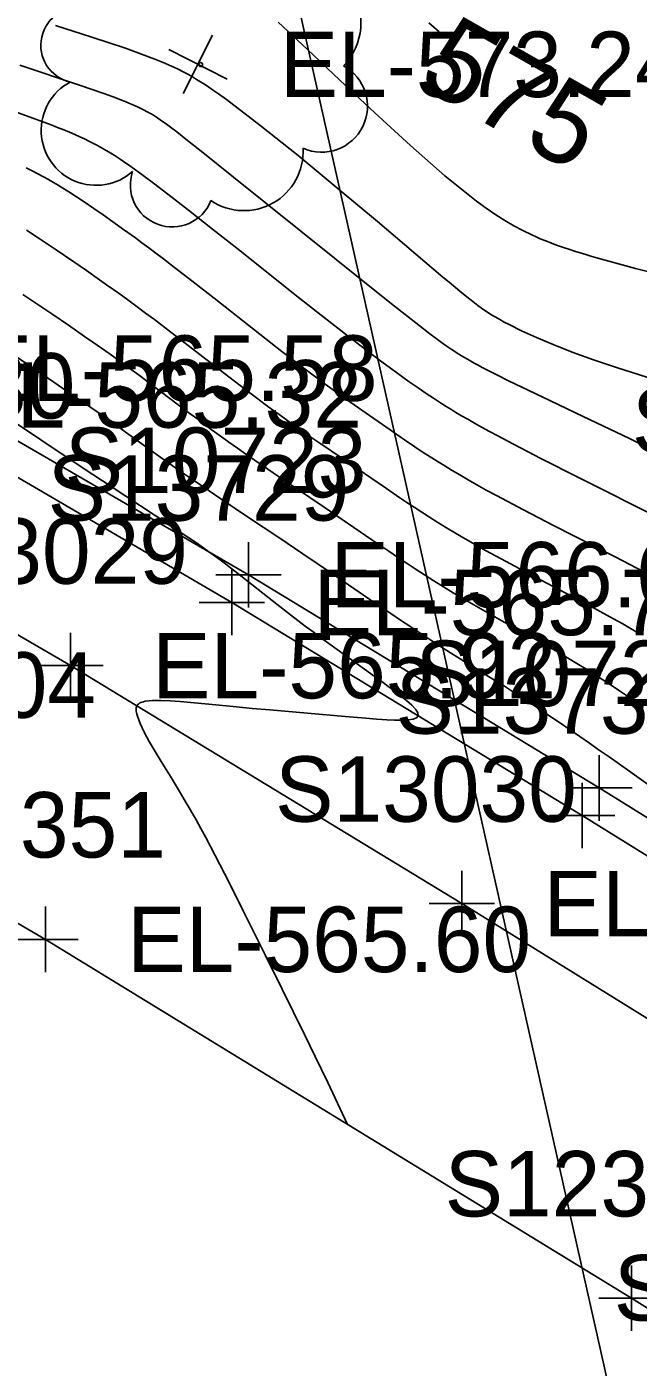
# Model space of a CAD drawing. Extents: x 1729869 to 1735532, y 648588 to 653771.
# Drawn here: x 1730731.9 to 1730769.3, y 652374.7 to 652456.6 of the extents above; entities that cross this region are included whole.
import ezdxf

# ---------------------------------------------------------------- set-up
doc = ezdxf.new("R2010")
doc.units = 0
for name, color, linetype in [('SURVEY - CONTOURS - Index with Text', 7, 'Continuous'), ('SURVEY - CONTOURS - Intermediate with optional Text', 7, 'Continuous'), ('SURVEY - DRAINAGE - Storm Sewer Text', 7, 'Continuous'), ('SURVEY - DTM - Breaklines', 7, 'Continuous'), ('SURVEY - DTM - Breaklines - Points - Elevations', 7, 'Continuous'), ('SURVEY - DTM - Breaklines - Points - Locators', 7, 'Continuous'), ('SURVEY - DTM - Breaklines - Points - Numbers', 7, 'Continuous'), ('SURVEY - TRANSPORTATION - Features', 7, 'Continuous'), ('SURVEY - TRANSPORTATION - Features - Points - Elevations', 7, 'Continuous'), ('SURVEY - TRANSPORTATION - Features - Points - Locators', 7, 'Continuous'), ('SURVEY - TRANSPORTATION - Features - Points - Numbers', 7, 'Continuous'), ('SURVEY - TRANSPORTATION - Roads', 7, 'Continuous'), ('SURVEY - TRANSPORTATION - Roads - Points - Elevations', 7, 'Continuous'), ('SURVEY - TRANSPORTATION - Roads - Points - Locators', 7, 'Continuous'), ('SURVEY - TRANSPORTATION - Roads - Points - Numbers', 7, 'Continuous'), ('SURVEY - UTILITIES - Poles and Miscellaneous - Points - Numbers', 7, 'Continuous'), ('SURVEY - VEGETATION - Features - Points - Elevations', 7, 'Continuous'), ('SURVEY - VEGETATION - Features - Points - Locators', 7, 'Continuous'), ('SURVEY - VEGETATION - Features with Text', 7, 'Continuous')]:
    doc.layers.add(name, color=color, linetype=linetype)

msp = doc.modelspace()

# ---------------------------------------------------------------- linework, layer by layer
at = {"layer": 'SURVEY - CONTOURS - Index with Text'}
for points in [[(1730757.118, 652456.338), (1730756.499, 652456.887)], [(1730769.662, 652423.314), (1730767.88, 652424.234), (1730764.101, 652426.166), (1730762.28, 652427.108), (1730760.621, 652427.988), (1730760.003, 652428.325), (1730759.425, 652428.647), (1730758.884, 652428.954), (1730758.379, 652429.247), (1730757.906, 652429.527), (1730757.463, 652429.795), (1730757.053, 652430.048), (1730756.667, 652430.291), (1730756.302, 652430.525), (1730755.956, 652430.752), (1730755.625, 652430.971), (1730755.002, 652431.391), (1730754.121, 652431.996), (1730752.387, 652433.198), (1730751.714, 652433.671), (1730751.353, 652433.928), (1730750.977, 652434.198), (1730750.581, 652434.486), (1730750.163, 652434.793), (1730749.723, 652435.12), (1730749.257, 652435.469), (1730748.766, 652435.841), (1730747.515, 652436.802), (1730746.164, 652437.855), (1730743.362, 652440.052), (1730742.01, 652441.108), (1730740.757, 652442.076), (1730740.269, 652442.45), (1730739.805, 652442.8), (1730739.366, 652443.13), (1730738.95, 652443.439), (1730738.555, 652443.73), (1730737.83, 652444.257), (1730737.177, 652444.723), (1730736.577, 652445.144), (1730736.018, 652445.53), (1730735.487, 652445.891), (1730734.965, 652446.239), (1730734.493, 652446.545), (1730734.118, 652446.783), (1730733.84, 652446.953), (1730733.552, 652447.126), (1730733.251, 652447.3), (1730732.934, 652447.477), (1730732.599, 652447.657), (1730732.248, 652447.838), (1730731.877, 652448.022)]]:
    msp.add_lwpolyline(points, dxfattribs=at)
at = {"layer": 'SURVEY - CONTOURS - Intermediate with optional Text'}
for points in [[(1730770.268, 652435.091), (1730767.969, 652435.806), (1730766.551, 652436.288), (1730765.259, 652436.761), (1730764.094, 652437.218), (1730763.06, 652437.655), (1730762.159, 652438.064), (1730761.392, 652438.439), (1730761.1, 652438.592), (1730760.83, 652438.739), (1730760.58, 652438.881), (1730760.349, 652439.019), (1730760.129, 652439.158), (1730759.916, 652439.3), (1730759.705, 652439.447), (1730759.491, 652439.604), (1730759.174, 652439.846), (1730758.802, 652440.142), (1730758.38, 652440.486), (1730757.726, 652441.029), (1730757.354, 652441.342), (1730753.346, 652444.73), (1730750.944, 652446.744), (1730748.495, 652448.764), (1730746.164, 652450.633), (1730744.114, 652452.195), (1730743.638, 652452.538), (1730743.336, 652452.75), (1730743.047, 652452.947), (1730742.77, 652453.13), (1730742.5, 652453.302), (1730742.236, 652453.464), (1730741.978, 652453.615), (1730741.719, 652453.76), (1730741.434, 652453.911), (1730741.172, 652454.043), (1730740.904, 652454.171), (1730740.628, 652454.298), (1730740.345, 652454.421), (1730740.052, 652454.544), (1730739.747, 652454.668), (1730737.948, 652455.329), (1730735.891, 652456.009), (1730733.671, 652456.707)], [(1730772.169, 652441.094), (1730769.12, 652441.872), (1730766.46, 652442.604), (1730766.087, 652442.715), (1730765.729, 652442.824), (1730765.384, 652442.932), (1730765.051, 652443.039), (1730764.73, 652443.147), (1730764.419, 652443.255), (1730764.129, 652443.359), (1730763.848, 652443.466), (1730763.573, 652443.574), (1730763.304, 652443.684), (1730763.04, 652443.798), (1730762.779, 652443.916), (1730762.231, 652444.181), (1730761.686, 652444.472), (1730761.137, 652444.792), (1730760.578, 652445.148), (1730760, 652445.543), (1730759.397, 652445.984), (1730757.471, 652447.533), (1730755.37, 652449.375), (1730753.198, 652451.37), (1730751.058, 652453.384), (1730749.052, 652455.278), (1730747.285, 652456.915)], [(1730771.773, 652429.989), (1730768.748, 652431.466), (1730765.919, 652432.824), (1730763.415, 652434.019), (1730761.368, 652435.008), (1730760.647, 652435.365), (1730760.027, 652435.681), (1730759.751, 652435.824), (1730759.497, 652435.959), (1730759.265, 652436.085), (1730759.05, 652436.203), (1730758.85, 652436.316), (1730758.663, 652436.425), (1730758.488, 652436.53), (1730758.321, 652436.632), (1730758.163, 652436.732), (1730758.01, 652436.832), (1730757.859, 652436.932), (1730757.556, 652437.141), (1730757.272, 652437.344), (1730756.933, 652437.593), (1730756.551, 652437.88), (1730755.873, 652438.401), (1730755.041, 652439.05), (1730754.388, 652439.565), (1730752.688, 652440.918), (1730750.717, 652442.499), (1730744.555, 652447.457), (1730742.57, 652449.046), (1730741.749, 652449.697), (1730741.079, 652450.219), (1730740.706, 652450.504), (1730740.374, 652450.749), (1730740.219, 652450.859), (1730740.073, 652450.96), (1730739.931, 652451.056), (1730739.791, 652451.147), (1730739.652, 652451.234), (1730739.513, 652451.317), (1730739.284, 652451.446), (1730739.045, 652451.572), (1730738.886, 652451.651), (1730738.719, 652451.73), (1730738.541, 652451.811), (1730738.352, 652451.894), (1730738.15, 652451.979), (1730737.936, 652452.066), (1730737.707, 652452.157), (1730737.463, 652452.25), (1730737.202, 652452.348), (1730736.629, 652452.556), (1730735.146, 652453.068), (1730731.485, 652454.291)], [(1730770.62, 652426.587), (1730765.684, 652429.068), (1730763.333, 652430.263), (1730761.268, 652431.335), (1730760.712, 652431.632), (1730760.195, 652431.91), (1730759.717, 652432.173), (1730759.275, 652432.419), (1730758.867, 652432.65), (1730758.491, 652432.867), (1730758.149, 652433.069), (1730757.833, 652433.259), (1730757.54, 652433.439), (1730757.267, 652433.61), (1730757.011, 652433.774), (1730756.77, 652433.931), (1730756.322, 652434.23), (1730755.896, 652434.522), (1730755.297, 652434.942), (1730754.6, 652435.44), (1730754.069, 652435.826), (1730753.468, 652436.271), (1730752.785, 652436.785), (1730752.006, 652437.38), (1730751.577, 652437.711), (1730750.092, 652438.871), (1730748.43, 652440.182), (1730744.933, 652442.956), (1730743.275, 652444.27), (1730741.795, 652445.433), (1730740.987, 652446.062), (1730740.276, 652446.608), (1730739.654, 652447.08), (1730739.116, 652447.482), (1730738.641, 652447.83), (1730738.212, 652448.137), (1730737.819, 652448.409), (1730737.63, 652448.537), (1730737.441, 652448.661), (1730737.253, 652448.783), (1730736.946, 652448.973), (1730736.627, 652449.162), (1730736.416, 652449.281), (1730736.195, 652449.402), (1730735.96, 652449.526), (1730735.709, 652449.652), (1730735.441, 652449.782), (1730735.157, 652449.914), (1730734.852, 652450.051), (1730734.526, 652450.192), (1730734.177, 652450.338), (1730733.803, 652450.489), (1730733.405, 652450.645), (1730732.069, 652451.142), (1730730.557, 652451.68)], [(1730769.366, 652419.546), (1730768.865, 652419.841), (1730768.338, 652420.144), (1730767.782, 652420.457), (1730766.563, 652421.123), (1730765.258, 652421.817), (1730762.545, 652423.244), (1730761.217, 652423.95), (1730759.962, 652424.635), (1730759.318, 652424.996), (1730758.706, 652425.348), (1730758.124, 652425.691), (1730757.569, 652426.024), (1730757.039, 652426.349), (1730756.533, 652426.666), (1730756.054, 652426.972), (1730755.594, 652427.271), (1730755.15, 652427.564), (1730754.72, 652427.851), (1730753.894, 652428.41), (1730751.275, 652430.205), (1730749.703, 652431.277), (1730749.286, 652431.564), (1730748.856, 652431.863), (1730748.416, 652432.171), (1730747.961, 652432.494), (1730747.49, 652432.832), (1730747, 652433.187), (1730746.492, 652433.561), (1730745.964, 652433.954), (1730744.962, 652434.711), (1730743.914, 652435.514), (1730741.77, 652437.169), (1730740.719, 652437.977), (1730739.713, 652438.741), (1730739.18, 652439.14), (1730738.667, 652439.52), (1730738.173, 652439.883), (1730737.696, 652440.228), (1730737.236, 652440.558), (1730736.792, 652440.874), (1730736.367, 652441.173), (1730735.557, 652441.736), (1730734.789, 652442.263), (1730733.705, 652442.999), (1730732.664, 652443.698), (1730731.907, 652444.198)], [(1730769.615, 652415.045), (1730769.13, 652415.383), (1730768.639, 652415.72), (1730768.141, 652416.057), (1730767.635, 652416.394), (1730767.127, 652416.727), (1730766.608, 652417.061), (1730766.076, 652417.395), (1730765.531, 652417.731), (1730764.97, 652418.069), (1730764.393, 652418.409), (1730763.56, 652418.886), (1730762.702, 652419.367), (1730760.956, 652420.335), (1730760.087, 652420.821), (1730759.236, 652421.307), (1730758.603, 652421.677), (1730757.985, 652422.047), (1730757.382, 652422.416), (1730756.792, 652422.783), (1730756.215, 652423.149), (1730755.651, 652423.513), (1730755.105, 652423.871), (1730754.568, 652424.227), (1730754.041, 652424.58), (1730753.012, 652425.278), (1730750.084, 652427.279), (1730749.226, 652427.861), (1730747.311, 652429.151), (1730746.321, 652429.824), (1730745.822, 652430.167), (1730745.314, 652430.52), (1730744.798, 652430.882), (1730744.272, 652431.255), (1730743.738, 652431.639), (1730743.194, 652432.035), (1730742.446, 652432.587), (1730741.686, 652433.155), (1730740.152, 652434.31), (1730739.389, 652434.881), (1730738.637, 652435.44), (1730738.083, 652435.845), (1730737.539, 652436.239), (1730737.003, 652436.623), (1730736.475, 652436.997), (1730735.956, 652437.361), (1730735.445, 652437.717), (1730734.458, 652438.396), (1730733.5, 652439.047), (1730731.671, 652440.28)], [(1730751.522, 652389.556), (1730750.307, 652392.108), (1730749.544, 652393.699), (1730748.89, 652395.044), (1730747.532, 652397.812), (1730746.487, 652399.929), (1730745.149, 652402.617), (1730744.469, 652403.974), (1730744.008, 652404.883), (1730743.724, 652405.435), (1730743.438, 652405.987), (1730743.148, 652406.538), (1730742.855, 652407.087), (1730742.559, 652407.631), (1730742.26, 652408.17), (1730741.906, 652408.796), (1730741.543, 652409.42), (1730741.168, 652410.049), (1730740.744, 652410.747), (1730740.139, 652411.73), (1730739.76, 652412.355), (1730739.406, 652412.962), (1730739.095, 652413.533), (1730738.845, 652414.051), (1730738.674, 652414.5), (1730738.64, 652414.624), (1730738.616, 652414.738), (1730738.605, 652414.815), (1730738.6, 652414.887), (1730738.601, 652414.954), (1730738.608, 652415.017), (1730738.622, 652415.074), (1730738.643, 652415.127), (1730738.668, 652415.171), (1730738.7, 652415.211), (1730738.737, 652415.248), (1730738.781, 652415.281), (1730738.83, 652415.31), (1730738.885, 652415.337), (1730738.96, 652415.365), (1730739.042, 652415.389), (1730739.152, 652415.414), (1730739.194, 652415.421), (1730739.606, 652415.464), (1730740.104, 652415.471), (1730740.671, 652415.449), (1730741.289, 652415.406), (1730741.942, 652415.348), (1730743.039, 652415.239), (1730744.74, 652415.068), (1730745.697, 652414.978), (1730746.762, 652414.883), (1730751.385, 652414.488), (1730752.647, 652414.379), (1730753.296, 652414.328), (1730753.61, 652414.305), (1730753.916, 652414.286), (1730754.4, 652414.264), (1730754.842, 652414.258), (1730755.224, 652414.275), (1730755.53, 652414.32), (1730755.744, 652414.401), (1730755.847, 652414.524), (1730755.826, 652414.7), (1730755.686, 652414.921), (1730755.446, 652415.179), (1730755.124, 652415.467), (1730754.74, 652415.778), (1730754.311, 652416.106), (1730754.012, 652416.327), (1730753.704, 652416.553), (1730753.066, 652417.011), (1730751.901, 652417.843), (1730750.886, 652418.576), (1730750.386, 652418.94), (1730749.895, 652419.301), (1730749.415, 652419.657), (1730748.94, 652420.012), (1730748.481, 652420.36), (1730748.036, 652420.7), (1730747.196, 652421.35), (1730746.344, 652422.017), (1730744.997, 652423.08), (1730744.375, 652423.563), (1730744.056, 652423.808), (1730743.729, 652424.054), (1730743.395, 652424.301), (1730743.051, 652424.55), (1730742.741, 652424.77), (1730742.424, 652424.991), (1730742.098, 652425.215), (1730741.422, 652425.67), (1730740.532, 652426.261), (1730737.129, 652428.494), (1730735.361, 652429.666), (1730732.77, 652431.392), (1730725.722, 652436.103)], [(1730770.622, 652409.793), (1730768.775, 652411.115), (1730767.505, 652412.015), (1730766.907, 652412.437), (1730766.31, 652412.855), (1730765.715, 652413.268), (1730765.123, 652413.677), (1730764.534, 652414.08), (1730763.956, 652414.471), (1730763.381, 652414.856), (1730762.808, 652415.236), (1730762.238, 652415.608), (1730761.671, 652415.974), (1730761.106, 652416.333), (1730760.658, 652416.613), (1730758.863, 652417.723), (1730758.409, 652418.006), (1730757.813, 652418.382), (1730757.212, 652418.766), (1730756.606, 652419.157), (1730755.996, 652419.555), (1730755.383, 652419.959), (1730754.767, 652420.367), (1730754.158, 652420.775), (1730752.94, 652421.598), (1730750.534, 652423.238), (1730748.781, 652424.432), (1730747.324, 652425.417), (1730745.476, 652426.654), (1730743.781, 652427.789), (1730742.668, 652428.544), (1730742.114, 652428.923), (1730741.561, 652429.305), (1730741.012, 652429.688), (1730740.465, 652430.073), (1730739.974, 652430.422), (1730738.014, 652431.829), (1730737.52, 652432.182), (1730736.96, 652432.579), (1730736.396, 652432.975), (1730735.828, 652433.371), (1730735.256, 652433.766), (1730734.108, 652434.553), (1730732.972, 652435.324), (1730731.281, 652436.462)]]:
    msp.add_lwpolyline(points, dxfattribs=at)
at = {"layer": 'SURVEY - DRAINAGE - Storm Sewer Text'}
msp.add_line((1730745.544, 652471.171), (1730769.273, 652365.628), dxfattribs=at)
at = {"layer": 'SURVEY - DTM - Breaklines'}
msp.add_lwpolyline([(1731001.804, 652246.837), (1730986.97, 652258.675), (1730981.863, 652262.82), (1730979.27, 652264.774), (1730974.15, 652268.679), (1730954.012, 652283.621), (1730933.622, 652298.476), (1730913.393, 652313.326), (1730892.983, 652327.762), (1730872.274, 652341.974), (1730851.38, 652356.104), (1730830.504, 652369.859), (1730809.435, 652383.476), (1730788.147, 652396.932), (1730766.91, 652410.117), (1730745.474, 652423.147), (1730723.671, 652435.774), (1730701.831, 652448.311), (1730680.069, 652460.611)], dxfattribs=at)
at = {"layer": 'SURVEY - DTM - Breaklines - Points - Locators'}
for p, q in [((1730745.474, 652425.147), (1730745.474, 652421.147)), ((1730747.474, 652423.147), (1730743.474, 652423.147)), ((1730766.91, 652412.117), (1730766.91, 652408.117)), ((1730768.91, 652410.117), (1730764.91, 652410.117))]:
    msp.add_line(p, q, dxfattribs=at)
at = {"layer": 'SURVEY - TRANSPORTATION - Features'}
msp.add_lwpolyline([(1730679.148, 652458.959), (1730700.909, 652446.658), (1730722.72, 652434.139), (1730744.445, 652421.455), (1730765.867, 652408.433), (1730787.104, 652395.248), (1730808.362, 652381.812), (1730829.417, 652368.203), (1730850.292, 652354.449), (1730871.15, 652340.343), (1730891.852, 652326.16), (1730912.257, 652311.717), (1730932.625, 652297.091), (1730952.92, 652282.174), (1730972.943, 652267.104), (1730977.983, 652263.095), (1730980.577, 652261.164), (1730985.786, 652257.149), (1731000.693, 652245.44)], dxfattribs=at)
at = {"layer": 'SURVEY - TRANSPORTATION - Features - Points - Locators'}
for p, q in [((1730744.445, 652423.455), (1730744.445, 652419.455)), ((1730746.445, 652421.455), (1730742.445, 652421.455)), ((1730765.867, 652410.433), (1730765.867, 652406.433)), ((1730767.867, 652408.433), (1730763.867, 652408.433))]:
    msp.add_line(p, q, dxfattribs=at)
at = {"layer": 'SURVEY - TRANSPORTATION - Roads'}
for points in [[(1730649.217, 652465.696), (1730673.763, 652452.23), (1730705.199, 652434.694), (1730734.582, 652417.595), (1730758.505, 652403.052), (1730784.006, 652387.256), (1730797.557, 652378.752), (1730819.407, 652364.667), (1730822.769, 652362.499)], [(1730842.714, 652331.091), (1730807.686, 652354.257), (1730790.839, 652365.031), (1730779.046, 652372.572), (1730768.87, 652378.929), (1730733.06, 652400.865), (1730706.465, 652416.408), (1730677.106, 652433.11), (1730650.892, 652447.449), (1730639.01, 652453.881), (1730623.049, 652462.2)]]:
    msp.add_lwpolyline(points, dxfattribs=at)
at = {"layer": 'SURVEY - TRANSPORTATION - Roads - Points - Locators'}
for p, q in [((1730734.582, 652419.595), (1730734.582, 652415.595)), ((1730736.582, 652417.595), (1730732.582, 652417.595)), ((1730758.505, 652405.052), (1730758.505, 652401.052)), ((1730760.505, 652403.052), (1730756.505, 652403.052)), ((1730733.06, 652402.865), (1730733.06, 652398.865)), ((1730735.06, 652400.865), (1730731.06, 652400.865)), ((1730768.87, 652380.929), (1730768.87, 652376.929)), ((1730770.87, 652378.929), (1730766.87, 652378.929))]:
    msp.add_line(p, q, dxfattribs=at)
at = {"layer": 'SURVEY - VEGETATION - Features - Points - Locators'}
for p, q in [((1730743.276, 652456.13), (1730741.474, 652452.558)), ((1730744.161, 652453.443), (1730740.589, 652455.245))]:
    msp.add_line(p, q, dxfattribs=at)
at = {"layer": 'SURVEY - VEGETATION - Features with Text'}
msp.add_circle((1730742.543, 652454.328), 0.117, dxfattribs=at)
for centre, radius, start, end in [((1730748.533, 652456.889), 3.808, 316.08606, 111.92455), ((1730735.083, 652455.51), 2.309, 78.25365, 256.99929), ((1730749.93, 652451.783), 2.809, 246.33896, 61.33924), ((1730736.154, 652450.304), 3.357, 118.27433, 311.69402), ((1730745.188, 652449.019), 3.62, 236.18005, 3.02572), ((1730740.801, 652446.961), 2.555, 160.893, 338.21215)]:
    msp.add_arc(centre, radius, start, end, dxfattribs=at)

# ---------------------------------------------------------------- texts
at = {"layer": 'SURVEY - CONTOURS - Index with Text'}
msp.add_text('575', height=5, rotation=330.37502, dxfattribs=at).set_placement((1730755.656, 652453.169))
at = {"layer": 'SURVEY - DTM - Breaklines - Points - Elevations'}
for s, p in [('EL-565.58', (1730728.671, 652433.774)), ('EL-566.05', (1730750.474, 652421.147))]:
    msp.add_text(s, height=4, dxfattribs=at).set_placement(p)
at = {"layer": 'SURVEY - DTM - Breaklines - Points - Numbers'}
for s, p in [('S10723', (1730734.234, 652428.147)), ('S10722', (1730755.67, 652415.117))]:
    msp.add_text(s, height=4, dxfattribs=at).set_placement(p)
at = {"layer": 'SURVEY - TRANSPORTATION - Features - Points - Elevations'}
for s, p in [('EL-565.32', (1730727.72, 652432.139)), ('EL-565.77', (1730749.445, 652419.455))]:
    msp.add_text(s, height=4, dxfattribs=at).set_placement(p)
at = {"layer": 'SURVEY - TRANSPORTATION - Features - Points - Numbers'}
for s, p in [('S13729', (1730733.19, 652426.455)), ('S13730', (1730754.454, 652413.433))]:
    msp.add_text(s, height=4, dxfattribs=at).set_placement(p)
at = {"layer": 'SURVEY - TRANSPORTATION - Roads - Points - Elevations'}
for s, p in [('EL-565.30', (1730710.199, 652432.694)), ('EL-565.92', (1730739.582, 652415.595)), ('EL-565.04', (1730711.465, 652414.408)), ('EL-566.41', (1730763.505, 652401.052)), ('EL-565.60', (1730738.06, 652398.865))]:
    msp.add_text(s, height=4, dxfattribs=at).set_placement(p)
at = {"layer": 'SURVEY - TRANSPORTATION - Roads - Points - Numbers'}
for s, p in [('S13029', (1730723.327, 652422.595)), ('S13030', (1730747.092, 652408.052)), ('S12351', (1730721.978, 652405.865)), ('S12350', (1730757.457, 652383.929)), ('S12349', (1730767.791, 652377.572))]:
    msp.add_text(s, height=4, dxfattribs=at).set_placement(p)
at = {"layer": 'SURVEY - UTILITIES - Poles and Miscellaneous - Points - Numbers'}
msp.add_text('S14403', height=4, dxfattribs=at).set_placement((1730768.9, 652430.563))
at = {"layer": 'SURVEY - VEGETATION - Features - Points - Elevations'}
msp.add_text('EL-573.24', height=4, dxfattribs=at).set_placement((1730747.375, 652452.344))

doc.saveas('drawing.dxf')
